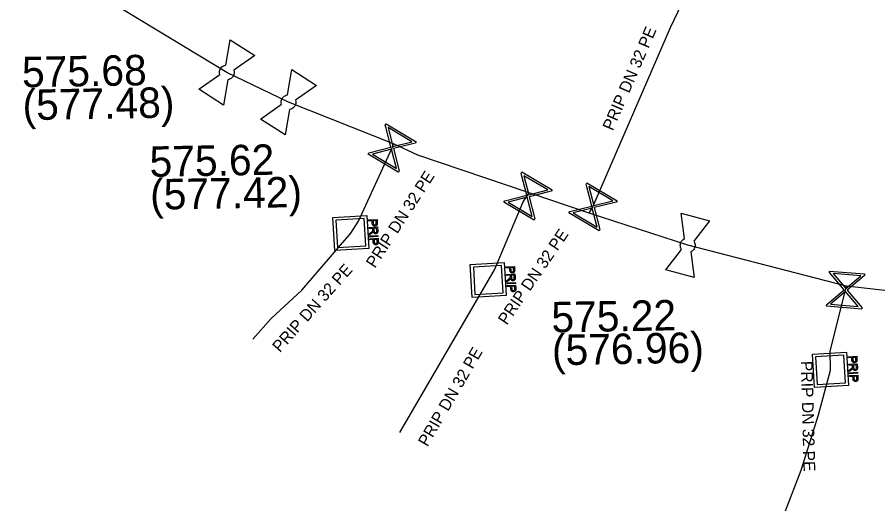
# Model space of a CAD drawing. Extents: x -643544 to -637295, y -1119190 to -1111715.
# Drawn here: x -641917.81 to -641881.12, y -1113645.1 to -1113624.06 of the extents above; entities that cross this region are included whole.
import ezdxf

# ---------------------------------------------------------------- set-up
doc = ezdxf.new("R2010")
doc.units = 0
for name, color, linetype in [('Default', 7, 'Continuous'), ('VP Lomový bod', 7, 'Continuous'), ('VP Lomový bod - popis', 7, 'Continuous'), ('VP Popis přípojky', 7, 'Continuous'), ('VP Přípojka', 7, 'Continuous'), ('VP Řad', 7, 'Continuous'), ('VP Šachta', 7, 'Continuous'), ('VP Šoupě', 7, 'Continuous')]:
    doc.layers.add(name, color=color, linetype=linetype)

msp = doc.modelspace()

# ---------------------------------------------------------------- linework, layer by layer
at = {"layer": 'Default'}
for points in [[(-641909.171, -1113626.5), (-641909.185, -1113626.45), (-641909.183, -1113626.397), (-641909.177, -1113626.311), (-641909.133, -1113626.242), (-641909.089, -1113626.173), (-641909.015, -1113626.134), (-641908.967, -1113626.108), (-641908.914, -1113626.101)], [(-641908.571, -1113626.32), (-641908.555, -1113626.371), (-641908.558, -1113626.425), (-641908.563, -1113626.509), (-641908.607, -1113626.578), (-641908.651, -1113626.647), (-641908.727, -1113626.688), (-641908.774, -1113626.713), (-641908.826, -1113626.72)], [(-641906.541, -1113627.77), (-641906.555, -1113627.72), (-641906.553, -1113627.667), (-641906.547, -1113627.581), (-641906.503, -1113627.512), (-641906.459, -1113627.443), (-641906.385, -1113627.404), (-641906.337, -1113627.378), (-641906.284, -1113627.371)], [(-641905.941, -1113627.59), (-641905.925, -1113627.641), (-641905.928, -1113627.695), (-641905.933, -1113627.779), (-641905.977, -1113627.848), (-641906.021, -1113627.917), (-641906.097, -1113627.958), (-641906.144, -1113627.983), (-641906.196, -1113627.99)], [(-641902.72, -1113633.224), (-641902.688, -1113633.202), (-641902.672, -1113633.187), (-641902.656, -1113633.173), (-641902.65, -1113633.162), (-641902.644, -1113633.15), (-641902.642, -1113633.139), (-641902.64, -1113633.132), (-641902.641, -1113633.113)], [(-641902.439, -1113633.158), (-641902.436, -1113633.205), (-641902.445, -1113633.231), (-641902.453, -1113633.256), (-641902.476, -1113633.273), (-641902.5, -1113633.289), (-641902.529, -1113633.29), (-641902.568, -1113633.293), (-641902.595, -1113633.27), (-641902.622, -1113633.247), (-641902.632, -1113633.196), (-641902.641, -1113633.215), (-641902.649, -1113633.225), (-641902.666, -1113633.247), (-641902.694, -1113633.267)], [(-641902.459, -1113632.814), (-641902.457, -1113632.85), (-641902.46, -1113632.869), (-641902.463, -1113632.895), (-641902.474, -1113632.914), (-641902.485, -1113632.933), (-641902.506, -1113632.945), (-641902.528, -1113632.956), (-641902.555, -1113632.958), (-641902.601, -1113632.961), (-641902.634, -1113632.934), (-641902.666, -1113632.907), (-641902.671, -1113632.831)], [(-641902.629, -1113632.829), (-641902.627, -1113632.875), (-641902.609, -1113632.893), (-641902.59, -1113632.911), (-641902.559, -1113632.909), (-641902.537, -1113632.908), (-641902.522, -1113632.896), (-641902.506, -1113632.884), (-641902.503, -1113632.866), (-641902.5, -1113632.853), (-641902.502, -1113632.82)], [(-641902.598, -1113633.157), (-641902.596, -1113633.19), (-641902.588, -1113633.208), (-641902.581, -1113633.226), (-641902.565, -1113633.234), (-641902.55, -1113633.243), (-641902.532, -1113633.242), (-641902.508, -1113633.24), (-641902.492, -1113633.221), (-641902.477, -1113633.202), (-641902.479, -1113633.161)], [(-641889.48, -1113633.957), (-641889.509, -1113633.914), (-641889.523, -1113633.862), (-641889.543, -1113633.778), (-641889.522, -1113633.699), (-641889.501, -1113633.62), (-641889.442, -1113633.56), (-641889.403, -1113633.521), (-641889.356, -1113633.498)], [(-641902.414, -1113633.615), (-641902.411, -1113633.65), (-641902.414, -1113633.67), (-641902.417, -1113633.696), (-641902.428, -1113633.715), (-641902.44, -1113633.734), (-641902.461, -1113633.745), (-641902.482, -1113633.757), (-641902.509, -1113633.759), (-641902.555, -1113633.761), (-641902.588, -1113633.735), (-641902.621, -1113633.708), (-641902.625, -1113633.632)], [(-641902.584, -1113633.63), (-641902.581, -1113633.676), (-641902.563, -1113633.694), (-641902.545, -1113633.712), (-641902.513, -1113633.71), (-641902.491, -1113633.709), (-641902.476, -1113633.697), (-641902.461, -1113633.685), (-641902.457, -1113633.666), (-641902.454, -1113633.654), (-641902.456, -1113633.621)], [(-641888.962, -1113633.604), (-641888.932, -1113633.648), (-641888.918, -1113633.7), (-641888.897, -1113633.782), (-641888.918, -1113633.861), (-641888.939, -1113633.94), (-641889, -1113634.002), (-641889.037, -1113634.04), (-641889.085, -1113634.063)], [(-641896.599, -1113634.814), (-641896.597, -1113634.85), (-641896.6, -1113634.869), (-641896.603, -1113634.895), (-641896.614, -1113634.914), (-641896.625, -1113634.933), (-641896.646, -1113634.945), (-641896.668, -1113634.956), (-641896.695, -1113634.958), (-641896.741, -1113634.961), (-641896.774, -1113634.934), (-641896.806, -1113634.907), (-641896.811, -1113634.831)], [(-641896.769, -1113634.829), (-641896.767, -1113634.875), (-641896.749, -1113634.893), (-641896.73, -1113634.911), (-641896.699, -1113634.909), (-641896.677, -1113634.908), (-641896.662, -1113634.896), (-641896.646, -1113634.884), (-641896.643, -1113634.866), (-641896.64, -1113634.853), (-641896.642, -1113634.82)], [(-641896.86, -1113635.224), (-641896.828, -1113635.202), (-641896.812, -1113635.187), (-641896.796, -1113635.173), (-641896.79, -1113635.162), (-641896.784, -1113635.15), (-641896.782, -1113635.139), (-641896.78, -1113635.132), (-641896.781, -1113635.113)], [(-641896.579, -1113635.158), (-641896.576, -1113635.205), (-641896.585, -1113635.231), (-641896.593, -1113635.256), (-641896.616, -1113635.273), (-641896.64, -1113635.289), (-641896.669, -1113635.29), (-641896.708, -1113635.293), (-641896.735, -1113635.27), (-641896.762, -1113635.247), (-641896.772, -1113635.196), (-641896.781, -1113635.215), (-641896.789, -1113635.225), (-641896.806, -1113635.247), (-641896.834, -1113635.267)], [(-641896.738, -1113635.157), (-641896.736, -1113635.19), (-641896.728, -1113635.208), (-641896.721, -1113635.226), (-641896.705, -1113635.234), (-641896.69, -1113635.243), (-641896.672, -1113635.242), (-641896.648, -1113635.24), (-641896.632, -1113635.221), (-641896.617, -1113635.202), (-641896.619, -1113635.161)], [(-641896.554, -1113635.615), (-641896.551, -1113635.65), (-641896.554, -1113635.67), (-641896.557, -1113635.696), (-641896.568, -1113635.715), (-641896.58, -1113635.734), (-641896.601, -1113635.745), (-641896.622, -1113635.757), (-641896.649, -1113635.759), (-641896.695, -1113635.761), (-641896.728, -1113635.735), (-641896.761, -1113635.708), (-641896.765, -1113635.632)], [(-641896.724, -1113635.63), (-641896.721, -1113635.676), (-641896.703, -1113635.694), (-641896.685, -1113635.712), (-641896.653, -1113635.71), (-641896.631, -1113635.709), (-641896.616, -1113635.697), (-641896.601, -1113635.685), (-641896.597, -1113635.666), (-641896.594, -1113635.654), (-641896.596, -1113635.621)], [(-641882.009, -1113638.644), (-641882.007, -1113638.68), (-641882.01, -1113638.699), (-641882.013, -1113638.725), (-641882.024, -1113638.744), (-641882.035, -1113638.763), (-641882.056, -1113638.775), (-641882.078, -1113638.786), (-641882.105, -1113638.788), (-641882.151, -1113638.791), (-641882.184, -1113638.764), (-641882.216, -1113638.737), (-641882.221, -1113638.661)], [(-641882.179, -1113638.659), (-641882.177, -1113638.705), (-641882.159, -1113638.723), (-641882.14, -1113638.741), (-641882.109, -1113638.739), (-641882.087, -1113638.738), (-641882.072, -1113638.726), (-641882.056, -1113638.714), (-641882.053, -1113638.696), (-641882.05, -1113638.683), (-641882.052, -1113638.65)], [(-641882.27, -1113639.054), (-641882.238, -1113639.032), (-641882.222, -1113639.017), (-641882.206, -1113639.003), (-641882.2, -1113638.992), (-641882.194, -1113638.98), (-641882.192, -1113638.969), (-641882.19, -1113638.962), (-641882.191, -1113638.943)], [(-641881.989, -1113638.988), (-641881.986, -1113639.035), (-641881.995, -1113639.061), (-641882.003, -1113639.086), (-641882.026, -1113639.103), (-641882.05, -1113639.119), (-641882.079, -1113639.12), (-641882.118, -1113639.123), (-641882.145, -1113639.1), (-641882.172, -1113639.077), (-641882.182, -1113639.026), (-641882.191, -1113639.045), (-641882.199, -1113639.055), (-641882.216, -1113639.077), (-641882.244, -1113639.097)], [(-641882.148, -1113638.987), (-641882.146, -1113639.02), (-641882.138, -1113639.038), (-641882.131, -1113639.056), (-641882.115, -1113639.064), (-641882.1, -1113639.073), (-641882.082, -1113639.072), (-641882.058, -1113639.07), (-641882.042, -1113639.051), (-641882.027, -1113639.032), (-641882.029, -1113638.991)], [(-641881.964, -1113639.445), (-641881.961, -1113639.48), (-641881.964, -1113639.5), (-641881.967, -1113639.526), (-641881.978, -1113639.545), (-641881.99, -1113639.564), (-641882.011, -1113639.575), (-641882.032, -1113639.587), (-641882.059, -1113639.589), (-641882.105, -1113639.591), (-641882.138, -1113639.565), (-641882.171, -1113639.538), (-641882.175, -1113639.462)], [(-641882.134, -1113639.46), (-641882.131, -1113639.506), (-641882.113, -1113639.524), (-641882.095, -1113639.542), (-641882.063, -1113639.54), (-641882.041, -1113639.539), (-641882.026, -1113639.527), (-641882.011, -1113639.515), (-641882.007, -1113639.496), (-641882.004, -1113639.484), (-641882.006, -1113639.451)]]:
    msp.add_open_spline(points, degree=3, dxfattribs=at)
at = {"layer": 'VP Lomový bod'}
for points in [[(-641908.914, -1113626.101), (-641908.724, -1113625.02), (-641907.671, -1113625.693), (-641908.571, -1113626.32)], [(-641909.016, -1113627.8), (-641910.069, -1113627.127), (-641909.171, -1113626.5)], [(-641906.284, -1113627.371), (-641906.094, -1113626.29), (-641905.041, -1113626.963), (-641905.941, -1113627.59)], [(-641908.826, -1113626.72), (-641909.016, -1113627.8)], [(-641906.386, -1113629.07), (-641907.439, -1113628.397), (-641906.541, -1113627.77)], [(-641906.196, -1113627.99), (-641906.386, -1113629.07)], [(-641889.356, -1113633.498), (-641889.5, -1113632.411), (-641888.292, -1113632.735), (-641888.962, -1113633.604)], [(-641888.94, -1113635.149), (-641890.148, -1113634.825), (-641889.48, -1113633.957)], [(-641889.085, -1113634.063), (-641888.94, -1113635.149)]]:
    msp.add_lwpolyline(points, dxfattribs=at)
at = {"layer": 'VP Přípojka'}
for points in [[(-641893.42, -1113632.41), (-641893.26, -1113632.14), (-641889.96, -1113624.5), (-641888.88, -1113622.22), (-641890.46, -1113616.83), (-641890.07, -1113616.29), (-641884.66, -1113607.92), (-641883.9, -1113607.72), (-641883.29, -1113607.98)], [(-641907.76, -1113637.78), (-641906.98, -1113636.9), (-641905.67, -1113635.69), (-641903.58, -1113633.26), (-641903.25, -1113632.75), (-641901.82, -1113629.63), (-641901.77, -1113629.46)], [(-641897.721, -1113635.269), (-641897.462, -1113634.822), (-641896.242, -1113631.932), (-641895.98, -1113631.55)], [(-641901.49, -1113641.76), (-641897.721, -1113635.269)], [(-641883.136, -1113639.111), (-641883.13, -1113639.09), (-641883.15, -1113638.3), (-641882.49, -1113635.69), (-641882.45, -1113635.53)], [(-641885.05, -1113645.1), (-641884.38, -1113643.37), (-641883.64, -1113641.01), (-641883.136, -1113639.111)]]:
    msp.add_lwpolyline(points, dxfattribs=at)
at = {"layer": 'VP Řad'}
msp.add_lwpolyline([(-641859.55, -1113636.01), (-641870.93, -1113636.46), (-641876.19, -1113636.24), (-641882.45, -1113635.53), (-641889.22, -1113633.78), (-641893.42, -1113632.41), (-641895.98, -1113631.55), (-641900.72, -1113629.94), (-641901.77, -1113629.46), (-641906.24, -1113627.68), (-641908.87, -1113626.41), (-641920.89, -1113619.14), (-641921.57, -1113618.77), (-641925.68, -1113616.26), (-641940.06, -1113607.75), (-641944.87, -1113604.7), (-641949.06, -1113602.26), (-641949.88, -1113601.76), (-641965.1, -1113592.66), (-641965.255, -1113592.575), (-641965.41, -1113592.49), (-641966.02, -1113592.14), (-641975.16, -1113586.77)], dxfattribs=at)
at = {"layer": 'VP Šachta'}
for points in [[(-641902.817, -1113633.923), (-641904.266, -1113634.008), (-641904.349, -1113632.597), (-641902.9, -1113632.512), (-641902.817, -1113633.923)], [(-641903.016, -1113632.64), (-641904.219, -1113632.71), (-641904.15, -1113633.88), (-641902.947, -1113633.81), (-641903.016, -1113632.64)], [(-641902.825, -1113632.701), (-641902.467, -1113632.68), (-641902.459, -1113632.814)], [(-641902.671, -1113632.831), (-641902.676, -1113632.739), (-641902.822, -1113632.747), (-641902.825, -1113632.701)], [(-641902.502, -1113632.82), (-641902.507, -1113632.729), (-641902.635, -1113632.736)], [(-641902.635, -1113632.736), (-641902.629, -1113632.829)], [(-641902.807, -1113633.02), (-641902.448, -1113632.999), (-641902.439, -1113633.158)], [(-641902.641, -1113633.113), (-641902.644, -1113633.059), (-641902.804, -1113633.068), (-641902.807, -1113633.02)], [(-641902.479, -1113633.161), (-641902.486, -1113633.049), (-641902.604, -1113633.056)], [(-641902.604, -1113633.056), (-641902.598, -1113633.157)], [(-641902.694, -1113633.267), (-641902.788, -1113633.335), (-641902.792, -1113633.275), (-641902.72, -1113633.224)], [(-641902.787, -1113633.384), (-641902.428, -1113633.363), (-641902.426, -1113633.409), (-641902.784, -1113633.43), (-641902.787, -1113633.384)], [(-641902.78, -1113633.502), (-641902.421, -1113633.481), (-641902.414, -1113633.615)], [(-641902.625, -1113633.632), (-641902.631, -1113633.54), (-641902.777, -1113633.548), (-641902.78, -1113633.502)], [(-641902.456, -1113633.621), (-641902.461, -1113633.53), (-641902.589, -1113633.537)], [(-641902.589, -1113633.537), (-641902.584, -1113633.63)], [(-641896.957, -1113635.923), (-641898.406, -1113636.008), (-641898.489, -1113634.597), (-641897.04, -1113634.512), (-641896.957, -1113635.923)], [(-641897.156, -1113634.64), (-641898.359, -1113634.71), (-641898.29, -1113635.88), (-641897.087, -1113635.81), (-641897.156, -1113634.64)], [(-641896.965, -1113634.701), (-641896.607, -1113634.68), (-641896.599, -1113634.814)], [(-641896.811, -1113634.831), (-641896.816, -1113634.739), (-641896.962, -1113634.747), (-641896.965, -1113634.701)], [(-641896.642, -1113634.82), (-641896.647, -1113634.729), (-641896.775, -1113634.736)], [(-641896.775, -1113634.736), (-641896.769, -1113634.829)], [(-641896.947, -1113635.02), (-641896.588, -1113634.999), (-641896.579, -1113635.158)], [(-641896.781, -1113635.113), (-641896.784, -1113635.059), (-641896.944, -1113635.068), (-641896.947, -1113635.02)], [(-641896.834, -1113635.267), (-641896.928, -1113635.335), (-641896.932, -1113635.275), (-641896.86, -1113635.224)], [(-641896.927, -1113635.384), (-641896.568, -1113635.363), (-641896.566, -1113635.409), (-641896.924, -1113635.43), (-641896.927, -1113635.384)], [(-641896.619, -1113635.161), (-641896.626, -1113635.049), (-641896.744, -1113635.056)], [(-641896.744, -1113635.056), (-641896.738, -1113635.157)], [(-641896.92, -1113635.502), (-641896.561, -1113635.481), (-641896.554, -1113635.615)], [(-641896.765, -1113635.632), (-641896.771, -1113635.54), (-641896.917, -1113635.548), (-641896.92, -1113635.502)], [(-641896.596, -1113635.621), (-641896.601, -1113635.53), (-641896.729, -1113635.537)], [(-641896.729, -1113635.537), (-641896.724, -1113635.63)], [(-641882.367, -1113639.753), (-641883.816, -1113639.838), (-641883.899, -1113638.427), (-641882.45, -1113638.342), (-641882.367, -1113639.753)], [(-641882.566, -1113638.47), (-641883.769, -1113638.54), (-641883.7, -1113639.71), (-641882.497, -1113639.64), (-641882.566, -1113638.47)], [(-641882.375, -1113638.531), (-641882.017, -1113638.51), (-641882.009, -1113638.644)], [(-641882.221, -1113638.661), (-641882.226, -1113638.569), (-641882.372, -1113638.577), (-641882.375, -1113638.531)], [(-641882.052, -1113638.65), (-641882.057, -1113638.559), (-641882.185, -1113638.566)], [(-641882.185, -1113638.566), (-641882.179, -1113638.659)], [(-641882.357, -1113638.85), (-641881.998, -1113638.829), (-641881.989, -1113638.988)], [(-641882.191, -1113638.943), (-641882.194, -1113638.889), (-641882.354, -1113638.898), (-641882.357, -1113638.85)], [(-641882.029, -1113638.991), (-641882.036, -1113638.879), (-641882.154, -1113638.886)], [(-641882.154, -1113638.886), (-641882.148, -1113638.987)], [(-641882.244, -1113639.097), (-641882.338, -1113639.165), (-641882.342, -1113639.105), (-641882.27, -1113639.054)], [(-641882.337, -1113639.214), (-641881.978, -1113639.193), (-641881.976, -1113639.239), (-641882.334, -1113639.26), (-641882.337, -1113639.214)], [(-641882.33, -1113639.332), (-641881.971, -1113639.311), (-641881.964, -1113639.445)], [(-641882.175, -1113639.462), (-641882.181, -1113639.37), (-641882.327, -1113639.378), (-641882.33, -1113639.332)], [(-641882.006, -1113639.451), (-641882.011, -1113639.36), (-641882.139, -1113639.367)], [(-641882.139, -1113639.367), (-641882.134, -1113639.46)]]:
    msp.add_lwpolyline(points, dxfattribs=at)
at = {"layer": 'VP Šoupě'}
for points in [[(-641902.08, -1113628.602), (-641900.792, -1113629.37), (-641900.826, -1113629.426), (-641900.951, -1113629.454), (-641901.765, -1113629.661), (-641901.526, -1113630.602), (-641901.56, -1113630.658), (-641902.848, -1113629.89), (-641902.814, -1113629.834), (-641901.872, -1113629.597), (-641902.079, -1113628.783), (-641902.114, -1113628.658), (-641902.08, -1113628.602)], [(-641901.993, -1113628.763), (-641901.787, -1113629.576), (-641900.976, -1113629.369), (-641901.993, -1113628.763)], [(-641901.642, -1113630.5), (-641901.85, -1113629.683), (-641902.666, -1113629.89), (-641901.642, -1113630.5)], [(-641896.29, -1113630.652), (-641895.002, -1113631.42), (-641895.036, -1113631.476), (-641895.161, -1113631.504), (-641895.975, -1113631.711), (-641895.736, -1113632.652), (-641895.77, -1113632.708), (-641897.058, -1113631.94), (-641897.024, -1113631.884), (-641896.082, -1113631.647), (-641896.289, -1113630.833), (-641896.324, -1113630.708), (-641896.29, -1113630.652)], [(-641896.203, -1113630.813), (-641895.997, -1113631.626), (-641895.186, -1113631.419), (-641896.203, -1113630.813)], [(-641893.52, -1113631.112), (-641892.232, -1113631.88), (-641892.266, -1113631.936), (-641892.391, -1113631.964), (-641893.205, -1113632.171), (-641892.966, -1113633.112), (-641893, -1113633.168), (-641894.288, -1113632.4), (-641894.254, -1113632.344), (-641893.312, -1113632.107), (-641893.519, -1113631.293), (-641893.554, -1113631.168), (-641893.52, -1113631.112)], [(-641893.433, -1113631.273), (-641893.227, -1113632.086), (-641892.416, -1113631.879), (-641893.433, -1113631.273)], [(-641895.852, -1113632.55), (-641896.06, -1113631.733), (-641896.876, -1113631.94), (-641895.852, -1113632.55)], [(-641893.082, -1113633.01), (-641893.29, -1113632.193), (-641894.106, -1113632.4), (-641893.082, -1113633.01)], [(-641883.177, -1113634.882), (-641881.682, -1113635.003), (-641881.687, -1113635.069), (-641881.788, -1113635.149), (-641882.427, -1113635.694), (-641881.798, -1113636.433), (-641881.803, -1113636.498), (-641883.298, -1113636.377), (-641883.293, -1113636.311), (-641882.551, -1113635.684), (-641883.096, -1113635.044), (-641883.182, -1113634.947), (-641883.177, -1113634.882)], [(-641883.027, -1113634.988), (-641882.484, -1113635.627), (-641881.847, -1113635.084), (-641883.027, -1113634.988)], [(-641881.948, -1113636.393), (-641882.494, -1113635.751), (-641883.135, -1113636.296), (-641881.948, -1113636.393)]]:
    msp.add_lwpolyline(points, dxfattribs=at)

# ---------------------------------------------------------------- texts
at = {"layer": 'VP Lomový bod - popis'}
for s, p in [('575.68', (-641917.593, -1113627.048)), ('(577.48)', (-641917.568, -1113628.447)), ('575.62', (-641912.153, -1113630.865)), ('(577.42)', (-641912.129, -1113632.264)), ('575.22', (-641895.022, -1113637.497)), ('(576.96)', (-641894.998, -1113638.897))]:
    msp.add_text(s, height=1.3, rotation=1, dxfattribs=at).set_placement(p)
at = {"layer": 'VP Popis přípojky'}
for rotation, p in [(66.6387, (-641892.413, -1113628.93)), (57.0948, (-641902.554, -1113634.786)), (55.7389, (-641896.934, -1113637.21)), (48.4474, (-641906.606, -1113638.382)), (59.86, (-641900.317, -1113642.4)), (271.4502, (-641884.4, -1113638.716))]:
    msp.add_text('PRIP DN 32 PE', height=0.5, rotation=rotation, dxfattribs=at).set_placement(p)

doc.saveas('drawing.dxf')
